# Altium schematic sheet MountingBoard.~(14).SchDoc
size Legal; Organization: Altium Limited; Address1: 3 Minna Close; Address2: Belrose; Address3: NSW 2085; Address4: Australia
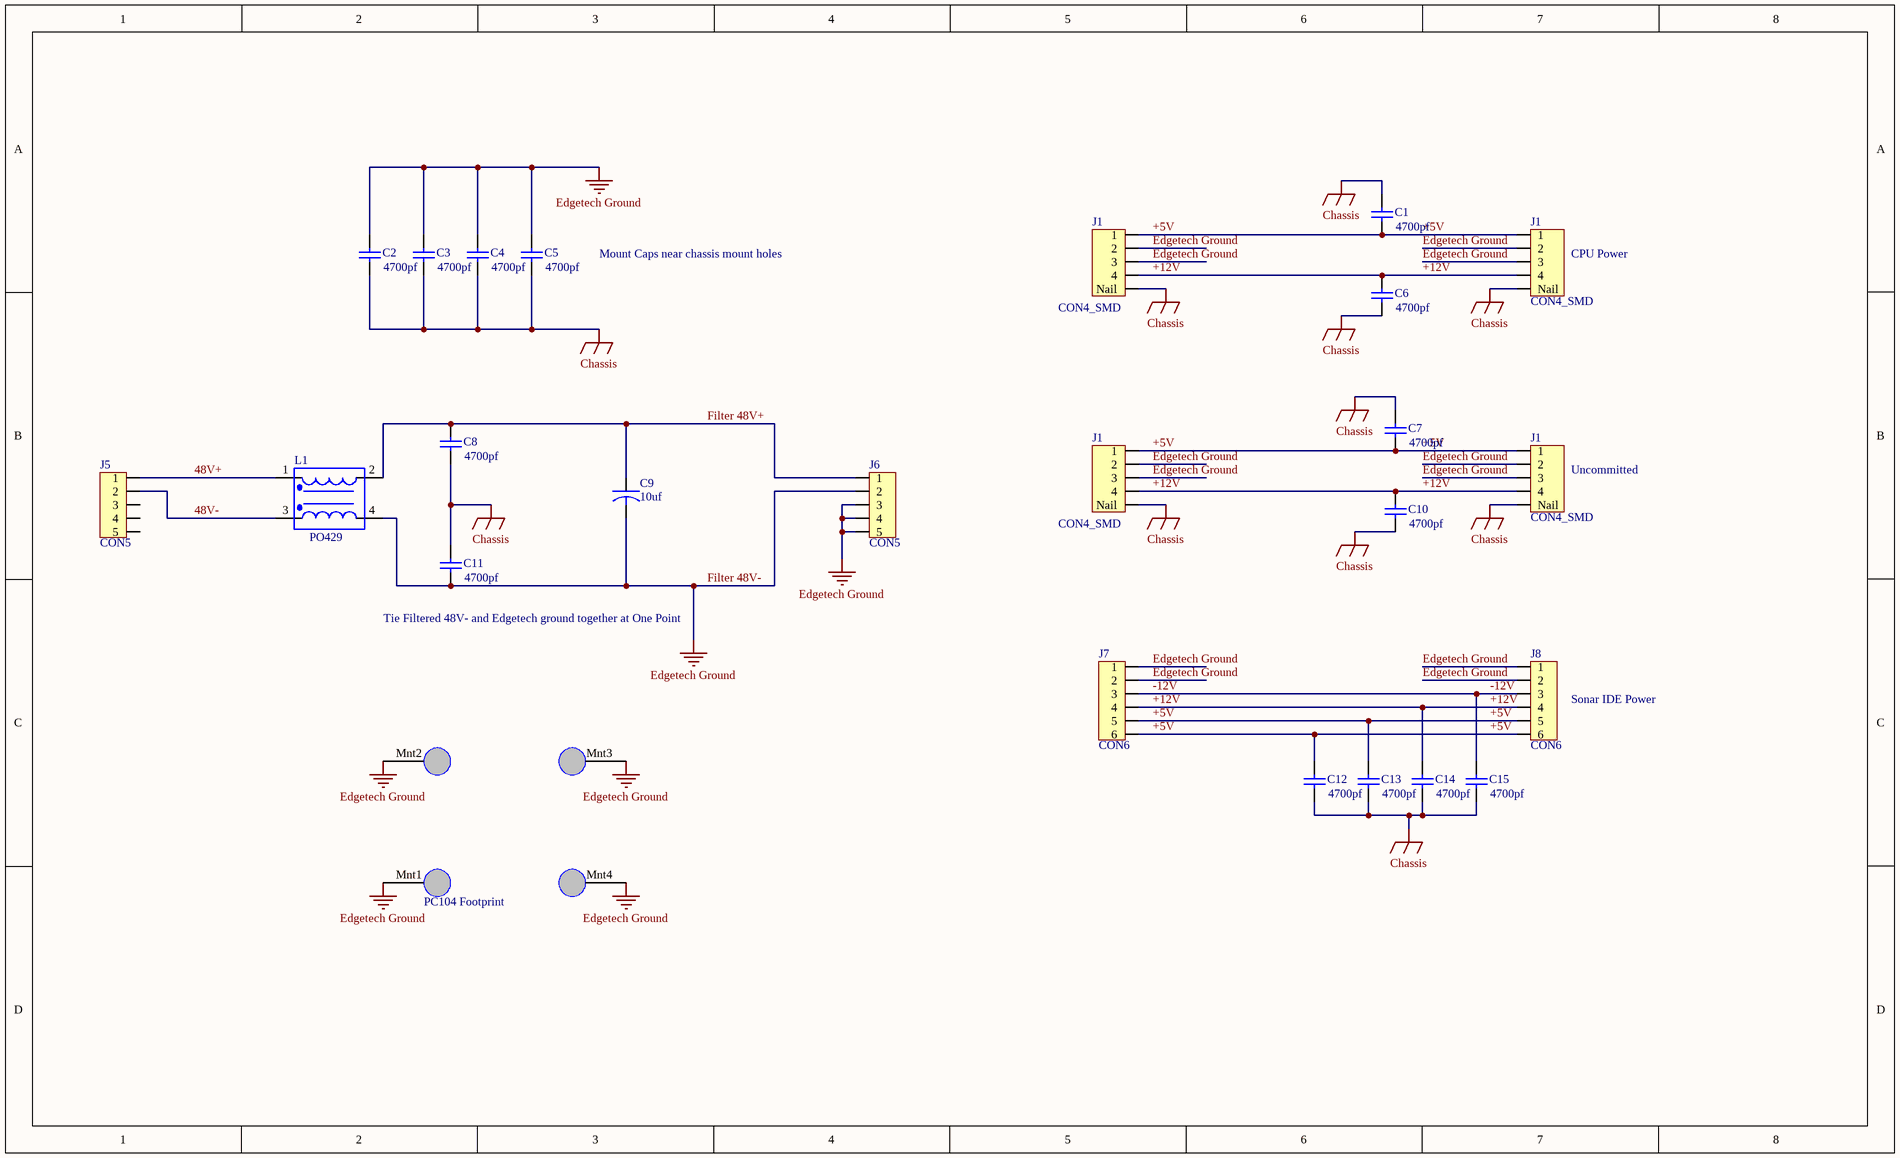
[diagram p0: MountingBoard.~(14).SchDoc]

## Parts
(Parts that share a designator on the sheet are numbered #1, #2 ... from top to bottom, then left to right.)
C1  value 4700pf  [7163]  (hidden comment: Cap Semi)
C2  value 4700pf  [7163]  (hidden comment: Cap Semi)
C3  value 4700pf  [7163]  (hidden comment: Cap Semi)
C4  value 4700pf  [7163]  (hidden comment: Cap Semi)
C5  value 4700pf  [7163]  (hidden comment: Cap Semi)
C6  value 4700pf  [7163]  (hidden comment: Cap Semi)
C7  value 4700pf  [7163]  (hidden comment: Cap Semi)
C8  value 4700pf  [7163]  (hidden comment: Cap Semi)
C9  10uf  [CAPSTICK-CS4-7-SMD]
C10  value 4700pf  [7163]  (hidden comment: Cap Semi)
C11  value 4700pf  [7163]  (hidden comment: Cap Semi)
C12  value 4700pf  [7163]  (hidden comment: Cap Semi)
C13  value 4700pf  [7163]  (hidden comment: Cap Semi)
C14  value 4700pf  [7163]  (hidden comment: Cap Semi)
C15  value 4700pf  [7163]  (hidden comment: Cap Semi)
F1  PC104 Footprint  [PC104 Footprint]
J1#1  CON4_SMD  [Microfit3-1x4 SMT RA Nail]
J1#2  CON4_SMD  [Microfit3-1x4 SMT RA Nail]
J1#3  CON4_SMD  [Microfit3-1x4 SMT RA Nail]
J1#4  CON4_SMD  [Microfit3-1x4 SMT RA Nail]
J5  CON5  [Microfit3-1x5 SMT RA Nail]
J6  CON5  [Microfit3-1x5 SMT RA Nail]
J7  CON6  [Microfit3-1x6 SMT RA Nail]
J8  CON6  [Microfit3-1x6 SMT RA Nail]
L1  ManufPartNo: PO429  [Pulse_BigFoot]

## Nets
Chassis: C1.2 C2.1 C3.1 C4.1 C5.1 C6.1 C7.2 C8.1 C10.1 C11.2 C12.1 C13.1 C14.1 C15.1 J1#1.nail(Nail) J1#2.nail(Nail) J1#3.nail(Nail) J1#4.nail(Nail)
Edgetech Ground: C2.2 C3.2 C4.2 C5.2 C9.2 C11.1 J1#1.2 J1#1.3 J1#2.2 J1#2.3 J1#3.2 J1#3.3 J1#4.2 J1#4.3 J6.2 J6.3 J6.4 J6.5 J7.1 J7.2 J8.1 J8.2 L1.4  [also labelled Filter 48V-]
48V+: J5.1 L1.1
48V-: J5.2 L1.3
+5V: C1.1 C7.1 C12.2 C13.2 J1#1.1 J1#2.1 J1#3.1 J1#4.1 J7.5 J7.6 J8.5 J8.6
+12V: C6.2 C10.2 C14.2 J1#1.4 J1#2.4 J1#3.4 J1#4.4 J7.4 J8.4
-12V: C15.2 J7.3 J8.3
Filter 48V+: C8.2 C9.1 J6.1 L1.2

Not connected (* = marked no-connect by the designer): F1 Mnt1 Mnt2 Mnt3 Mnt4; J5 3 4 5

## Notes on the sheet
- Mount Caps near chassis mount holes
- (near J1#2) CPU Power
- (near J1#4) Uncommitted
- (near C11) Tie Filtered 48V- and Edgetech ground together at One Point
- (near J8) Sonar IDE Power
- Labels drawn without touching a wire or pin: Edgetech Ground

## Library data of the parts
C1-C8 C10-C15 = Cap Semi: Capacitor (Semiconductor SIM Model); Manufacturer: Panasonic; ManufPartNo: ECK-TBC472MF; VendorPartNo: P10743TR-ND; Vendor: Digikey
C9 = CAPACITOR: ManufPartNo: 106K100CS4G; Manufacturer: ITW Paktron; Vendor: Future Electronics; Value: 10
J5 J6 = CON5: Connector; ManufPartNo: 43065-0513; Manufacturer: Molex; VendorPartNo: WM1898-ND; Vendor: Digikey
J7 J8 = CON6: Connector
L1 = COMMON MODE CHOKE: Manufacturer: Pulse Engineering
